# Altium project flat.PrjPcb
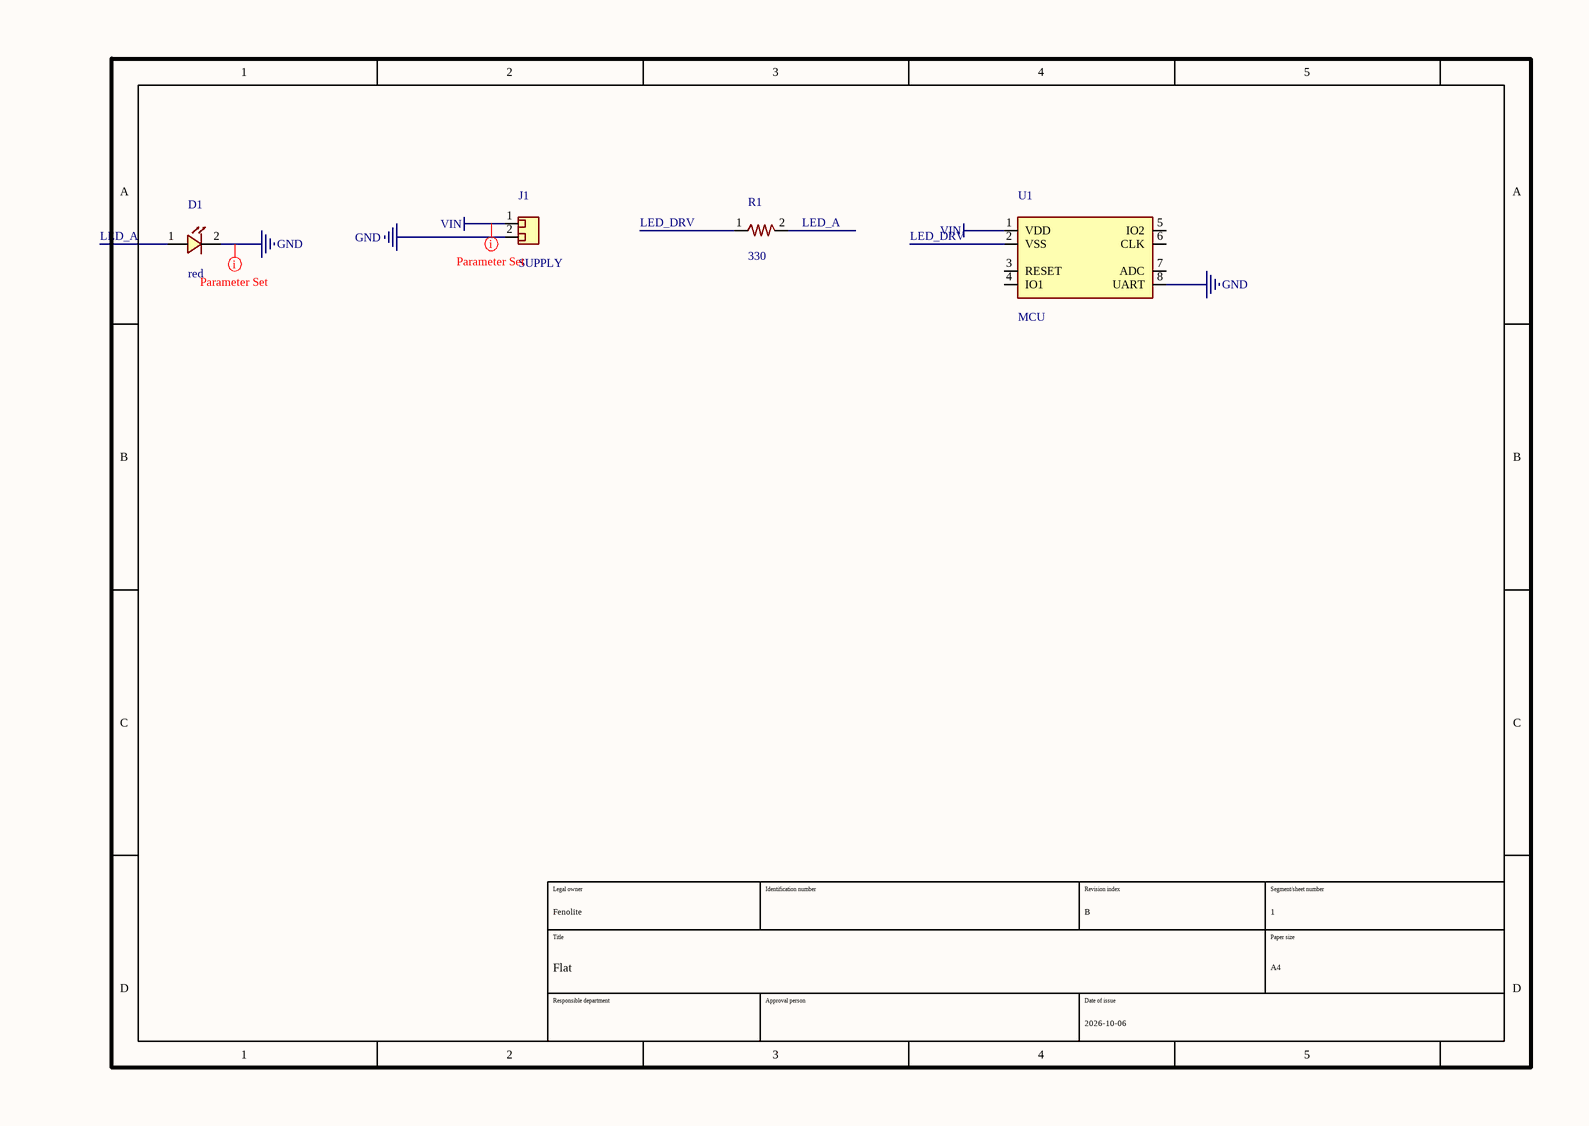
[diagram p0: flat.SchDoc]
1 sheet, 4 parts. Net scope: global (net labels, ports and power ports of the same name join across sheets).
Board file: flat.PcbDoc

## Sheet flat.SchDoc: Flat
size 297 x 209 mm; Revision: B; Date: 2026-10-06; Organization: Fenolite; SheetNumber: 1; SheetTotal: 1

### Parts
D1  red  [LED0603_Kingbright_APT1608SURCK]
J1  SUPPLY  [Header_1x2_P2.54]
R1  330  [Chip_0603]
U1  MCU  [DIP8_Microchip_P]

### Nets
GND: D1.2(K) J1.2(Passive) U1.8(UART)
VIN: J1.1(Passive) U1.1(VDD)
LED_A: D1.1(A) R1.2(B)
LED_DRV: R1.1(A) U1.2(VSS)

Not connected (* = marked no-connect by the designer): U1 3(RESET) 4(IO1) 5(IO2) 6(CLK) 7(ADC)

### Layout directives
net class PWR: GND, VIN

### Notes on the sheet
- 1
- 2
- 3
- 4
- 5
- A
- B
- C
- Legal owner
- Title
- Identification number
- Revision index
- Segment/sheet number
- Paper size
- D
- Responsible department
- Approval person
- Date of issue
- A4

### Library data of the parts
D1 = LED: pin to pad: 1>2 2>1
J1 = Connector_2
R1 = Resistor
U1 = Microcontroller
